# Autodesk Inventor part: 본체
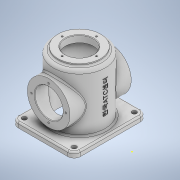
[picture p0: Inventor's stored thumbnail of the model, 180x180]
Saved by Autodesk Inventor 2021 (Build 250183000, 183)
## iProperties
Created: 2021-02
Part Number: 본체
Material: 일반
Document SubType Name: Modeling
Designer: 201-09
Density: 1 g/cm^3
Appearance: 기본값
Author: 201-09
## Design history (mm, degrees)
sketch "스케치1"
  geometry: L1 (60, 70)-(-60, 70); L2 (-60, 70)-(-60, -70); L3 (-60, -70)-(60, -70); L4 (60, -70)-(60, 70); L5 (60, 70)-(-60, -70); L6 (-60, 70)-(60, -70); 1 further point
  constraints: 12 end point, 2 midpoint, 2 parallel, 1 horizontal, 1 perpendicular
  dimensions: "d0" = 120 distance of L3.end L2.end; "d1" = 140 distance between parallel lines of L1 L3
extrude "돌출1" new body sketch "스케치1" distance "d2" = 10; taper "d3" = 0 deg
sketch "스케치2"
  geometry: C1 r 50 at (0, 0); 1 further point
  constraints: 1 centre point, 1 coincident
  dimensions: "d4" = 100 diameter of C1
extrude "돌출2" join sketch "스케치2" distance "d5" = 110; taper "d6" = 0 deg
sketch "스케치3"
  geometry: C1 r 41 at (0, 0); 1 further point
  constraints: 1 centre point, 1 coincident
  dimensions: "d7" = 82 diameter of C1
extrude "돌출3" join sketch "스케치3" distance "d8" = 5; taper "d9" = 0 deg
fillet "모깎기1" dims "d10" = 12
sketch "스케치5"
  geometry: L1 (-48, -70)-(48, -70) reference; L2 (60, -58)-(60, 58) reference; L3 (48, 70)-(-48, 70) reference; L4 (-60, 58)-(-60, -58) reference; C1 r 50 at (0, 0) reference; A1 r 12 centre (-48, -58) between (-60, -58) and (-48, -70) reference; A2 r 12 centre (48, -58) between (48, -70) and (60, -58) reference; A3 r 12 centre (48, 58) between (60, 58) and (48, 70) reference; A4 r 12 centre (-48, 58) between (-48, 70) and (-60, 58) reference; 5 further points
  constraints: 4 coincident
hole "구멍1" sketch "스케치5" at (-48, -58), (-48, 58), (48, 58), (48, -58) diameter "d11" = 9; stored, may be unused: countersink angle "d15" = 90 deg, drill point angle "d17" = 118 deg; dims "d12" = 6, "d13" = 4, "d14" = 2, "d16" = 8
sketch "스케치6"
  geometry: C1 r 27 at (0, 0); 1 further point
  constraints: 1 centre point, 1 coincident
  dimensions: "d18" = 54 diameter of C1
extrude "돌출4" cut sketch "스케치6" distance "d19" = 13; taper "d20" = 0 deg
sketch "스케치7"
  geometry: C1 r 42 at (0, 0); 1 further point
  constraints: 1 centre point, 1 coincident
  dimensions: "d21" = 84 diameter of C1
sketch "스케치8" dims "d24" = 66
  geometry: L1 (-92.25, 0)-(133.5, 0) reference; L2 (0, 98)-(0, -98) reference; C1 r 41 at (0, 0) reference; 6 further points
  constraints: 2 vertical alignment, 1 coincident, 1 point on line, 7 other
  dimensions: "d27" = 360 deg dimension on C1.centre point (0, 33) (derived)
hole "구멍2" sketch "스케치8" at (0, 33), (-33, 0), (0, -33), (33, 0) diameter "d29" = 3.242; stored, may be unused: countersink angle "d33" = 90 deg, drill point angle "d35" = 118 deg; dims "d30" = 8, "d31" = 4, "d32" = 2, "d34" = 10
extrude "돌출8" cut sketch "스케치7" extent not by distance; stored distance "d43" = 0; taper "d44" = 0 deg
node "작업 평면1"
sketch "스케치12"
  geometry: L1 (-48, 0)-(48, 0) reference; C1 r 41 at (0, 60); 2 further points
  constraints: 1 centre point, 1 midpoint, 1 vertical alignment
  dimensions: "d58" = 82 diameter of C1; "d59" = 60 distance from line of L1 C1.centre
extrude "돌출9" join sketch "스케치12" stored distance "d61" = 118; taper "d62" = 0 deg
sketch "스케치13"
  geometry: C1 r 41 at (0, 0) reference; C2 r 27 at (0, 0); 1 further point
  constraints: 1 centre point, 1 coincident
  dimensions: "d63" = 54 diameter of C2
extrude "돌출10" cut sketch "스케치13" extent not by distance; stored distance "d64" = 0; taper "d65" = 0 deg
sketch "스케치14" dims "d66" = 66
  geometry: C1 r 41 at (0, 0) reference; 6 further points
  constraints: 2 vertical alignment, 1 coincident, 7 other
  dimensions: "d69" = 360 deg dimension on C1.centre point (0, 33) (derived)
hole "구멍4" sketch "스케치14" at (0, 33), (-33, 0), (0, -33), (33, 0) diameter "d71" = 3.242; stored, may be unused: countersink angle "d75" = 90 deg, drill point angle "d77" = 118 deg; dims "d72" = 8, "d73" = 4, "d74" = 2, "d76" = 10
node "작업 평면2"
sketch "스케치15"
  geometry: 1 further point
sketch "스케치16"
  geometry: L1 (0, 58)-(0, -58) reference; 2 further points
  constraints: 1 horizontal alignment, 1 other
  dimensions: "d79" = 66 distance from line of L1 point (66, 0)
feature "엠보싱1" sketch "스케치16" dims "d0" = 120, "d1" = 140, "d80" = 0.5, "d81" = 0
fillet "모깎기2" dims "d82" = 3
fillet "모깎기3" dims "d83" = 3
fillet "모깎기4" dims "d84" = 3
fillet "모깎기5" dims "d85" = 6
fillet "모깎기6" dims "d86" = 3
chamfer "모따기1" distance "d87" = 1; stored, may be unused: second distance "d88" = 2, angle "d89" = 45 deg
fillet "모깎기7" dims "d90" = 3
node "솔리드1"
mirror "미러1"
mirror "미러2"
mirror "미러3"
node "투영된 루프1"
feature "A9D066F2-1C7D-4E18-AEED-F7BC21143FA4" dims "d11" = 9, "d12" = 6, "d13" = 4, "d14" = 2, "d15" = 90 deg, "d16" = 8, "d17" = 118 deg
other parameters: "d57" = 59, "d78" = 101.25
